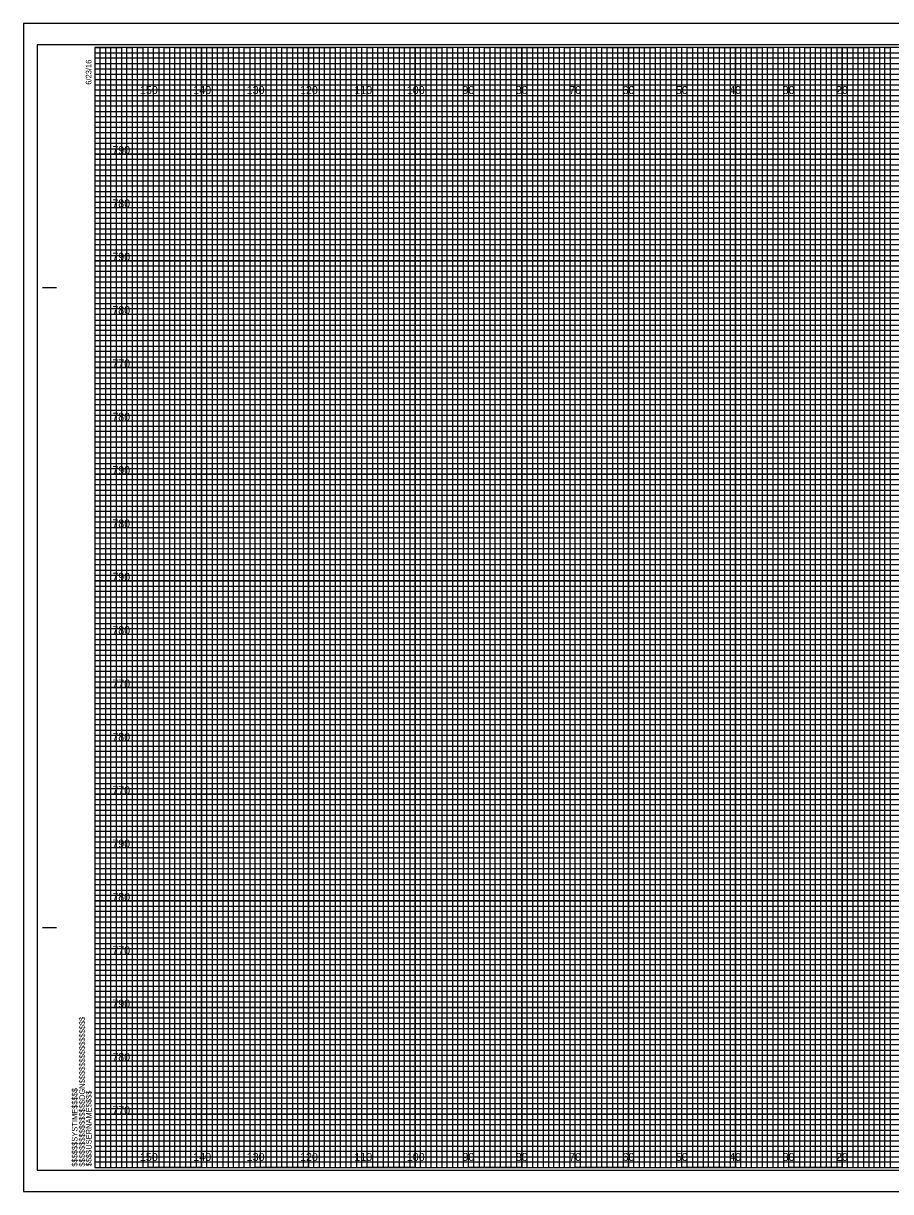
# Model space of a CAD drawing. Extents: x -13 to 323, y -5 to 215.
# Drawn here: x -13.4 to 149.1, y -4.5 to 214.5 of the extents above; entities that cross this region are included whole.
import ezdxf

# ---------------------------------------------------------------- set-up
doc = ezdxf.new("R2010")
doc.units = 0
for name, color, linetype in [('Exist Cross Section Cell', 7, 'Continuous'), ('Exist XS Center Line Elevation Label', 7, 'Continuous'), ('Exist XS Ground Line', 7, 'Continuous'), ('Prop CMT Pvmt Course 2', 7, 'Continuous'), ('Prop XS DDE', 7, 'Continuous'), ('Prop XS DDE Elevations', 7, 'Continuous'), ('Prop XS Elevation Labels', 7, 'Continuous'), ('Prop XS Offset Labels', 7, 'Continuous'), ('Sheet Cutting Line CELL', 7, 'Continuous'), ('Sheet DOT Grid CELL', 7, 'Continuous'), ('Sheet Plot Border Outside CELL', 7, 'Continuous')]:
    doc.layers.add(name, color=color, linetype=linetype)

msp = doc.modelspace()

# ---------------------------------------------------------------- linework, layer by layer
at = {"layer": 'Exist Cross Section Cell'}
for p, q in [((10, 210), (0, 210)), ((10, 0), (10, 210)), ((30, 210), (20, 210)), ((20, 210), (20, 0)), ((30, 0), (30, 210)), ((50, 210), (40, 210)), ((40, 210), (40, 0)), ((50, 0), (50, 210)), ((70, 210), (60, 210)), ((60, 210), (60, 0)), ((70, 0), (70, 210)), ((90, 210), (80, 210)), ((80, 210), (80, 0)), ((90, 0), (90, 210)), ((110, 210), (100, 210)), ((100, 210), (100, 0)), ((110, 0), (110, 210)), ((130, 210), (120, 210)), ((120, 210), (120, 0)), ((130, 0), (130, 210)), ((150, 210), (140, 210)), ((140, 210), (140, 0)), ((20, 0), (10, 0)), ((40, 0), (30, 0)), ((60, 0), (50, 0)), ((80, 0), (70, 0)), ((100, 0), (90, 0)), ((120, 0), (110, 0)), ((140, 0), (130, 0))]:
    msp.add_line(p, q, dxfattribs=at)
for points in [[(0, 200), (320, 200), (320, 190), (0, 190)], [(0, 180), (320, 180), (320, 170), (0, 170)], [(0, 160), (320, 160), (320, 150), (0, 150)], [(0, 140), (320, 140), (320, 130), (0, 130)], [(0, 120), (320, 120), (320, 110), (0, 110)], [(0, 100), (320, 100), (320, 90), (0, 90)], [(0, 80), (320, 80), (320, 70), (0, 70)], [(0, 60), (320, 60), (320, 50), (0, 50)], [(0, 40), (320, 40), (320, 30), (0, 30)], [(0, 20), (320, 20), (320, 10), (0, 10)]]:
    msp.add_lwpolyline(points, dxfattribs=at)
at = {"layer": 'Exist XS Center Line Elevation Label'}
for p, q in [((0, 209), (260, 209)), ((260, 207.98), (0, 207.98)), ((0, 207.98), (0, 207)), ((0, 207), (260, 207)), ((260, 205.89), (0, 205.89)), ((0, 205.89), (0, 204)), ((0, 204), (320, 204))]:
    msp.add_line(p, q, dxfattribs=at)
for points in [[(0, 203), (270, 203), (320, 203), (320, 202), (0, 202)], [(0, 201), (320, 201), (320, 199), (0, 199)], [(0, 198), (320, 198), (320, 197), (0, 196.98)], [(0, 196), (320, 196), (320, 194), (0, 194)], [(0, 193), (320, 193), (320, 192), (0, 192)], [(0, 191), (320, 191), (320, 189), (0, 189)], [(0, 188), (320, 188), (320, 187), (0, 187)], [(0, 186), (320, 186), (320, 184), (0, 184)], [(0, 183), (320, 183), (320, 182), (0, 182)], [(0, 181), (320, 181), (320, 179), (0, 179)], [(0, 178), (320, 178), (320, 177), (0, 177)], [(0, 176), (320, 176), (320, 173.95), (320, 173), (320, 172), (0, 172)], [(0, 174), (320, 174), (320, 173), (0, 173)], [(0, 171), (320, 171), (320, 169), (0, 169.03)], [(0, 169.03), (320, 169), (320, 168), (0, 168)], [(0, 167), (320, 167), (320, 166), (0, 166)], [(0, 164), (320, 164), (320, 163), (0, 163)], [(0, 162), (320, 162), (320, 161), (0, 161)], [(-0.07, 158.89), (320, 158.89), (320, 157.88), (-0.07, 157.88)], [(0, 157), (320, 157), (320, 156), (0, 156)], [(0, 154), (320, 154), (320, 153), (0, 153)], [(0, 152), (320, 152), (320, 151), (0, 151)], [(0, 149), (320, 149), (320, 148), (0, 148)], [(0, 147), (320, 147), (320, 146), (0, 146)], [(0, 144), (320, 144), (320, 143), (0, 143)], [(0, 142), (320, 142), (320, 141), (0, 141)], [(0, 139), (320, 139), (319.99, 137.98), (0, 138)], [(0, 137), (320, 137), (320, 136), (0, 136)], [(0, 134), (320, 134), (320, 133), (0, 133)], [(0, 132), (320, 132), (320, 131), (0, 131)], [(0, 129), (320, 129), (320, 128), (0, 128)], [(0, 127), (320, 127), (320, 126), (0, 126)], [(0, 124), (320, 124), (320, 123), (0, 123)], [(0, 122), (320, 122), (320, 121), (0, 121)], [(0, 119), (320, 119), (320, 118), (0, 118)], [(0, 116.99), (320.07, 116.91), (320, 116), (0, 116)], [(0, 114), (320, 114), (320, 113), (0, 113)], [(0, 112), (320, 112), (320, 111), (0, 111)], [(0, 109), (320, 109), (320, 108), (0, 108)], [(0, 107), (320, 107), (320, 106), (0, 106)], [(0, 104), (320, 104), (320, 103), (0, 103)], [(0, 102), (320, 102), (320, 101), (0, 101)], [(0, 99), (320, 99), (320, 98), (0, 98)], [(0, 97), (320, 97), (320, 96), (0, 96)], [(0, 94), (320, 94), (320, 93), (0, 93)], [(0, 92), (320, 92), (320, 91), (0, 91)], [(0, 89), (320, 89), (320, 88), (0, 88)], [(0, 87), (320, 87), (320, 86), (0, 86)], [(0, 84), (320, 84), (320, 83), (0, 83)], [(0, 82), (320, 82), (320, 81), (0, 81)], [(0, 79), (320, 79), (319.99, 77.98), (0, 78)], [(0, 77), (320, 77), (320, 76), (0, 76)], [(0, 74), (320, 74), (320, 73), (0, 73)], [(0, 72), (320, 72), (320, 71), (0, 71)], [(0, 69), (320, 69), (320, 68), (0, 68)], [(0, 67), (320, 67), (320, 66), (0, 66)], [(0, 64), (320, 64), (320, 63), (0, 63)], [(0, 62), (320, 62), (320, 61), (0, 61)], [(0, 59), (320, 59), (320, 58), (0, 58)], [(0, 56.99), (320.07, 56.91), (320, 56), (0, 56)], [(0, 54), (320, 54), (320, 53), (0, 53)], [(0, 52), (320, 52), (320, 51), (0, 51)], [(0, 49), (320, 49), (320, 48), (0, 48)], [(0, 47), (320, 47), (320, 46), (0, 46)], [(0, 44), (320, 44), (320, 43), (0, 43)], [(0, 42), (320, 42), (320, 41), (0, 41)], [(0, 39), (320, 39), (320, 38), (0, 38)], [(0, 37), (320, 37), (320, 36), (0, 36)], [(0, 34), (320, 34), (320, 33), (0, 33)], [(0, 32), (320, 32), (320, 31), (0, 31)], [(0, 29), (320, 29), (320, 28), (0, 28)], [(0, 27), (320, 27), (320, 26), (0, 26)], [(0, 24), (320, 24), (320, 23), (0, 23)], [(0, 22), (320, 22), (320, 21), (0, 21)], [(0, 19), (320, 19), (320, 18), (0, 18)], [(0, 17), (320, 17), (320, 16), (0, 16)], [(0, 14), (320, 14), (320, 13), (0, 13)], [(0, 12), (320, 12), (320, 11), (0, 11)], [(0, 9), (320, 9), (320, 8), (0, 8)], [(0, 7), (320, 7), (320, 6), (0, 6)], [(0, 4), (320, 4), (320, 3), (0, 3)], [(0, 2), (320, 2), (320, 1), (0, 1)]]:
    msp.add_lwpolyline(points, dxfattribs=at)
at = {"layer": 'Exist XS Ground Line'}
for points in [[(0, 210), (5, 210), (5, 0), (15, 0), (15, 210), (25, 210), (25, 0), (35, 0), (35, 210), (45, 210), (45, 0), (55, 0), (55, 210), (65, 210), (65, 0), (75, 0), (75, 210), (85, 210), (85, 0), (95, 0), (95, 210), (105, 210), (105, 0), (115, 0), (115, 210), (125, 210), (125, 0), (135, 0), (135, 210), (145, 210), (145, 0), (155, 0)], [(0, 205), (275, 205)], [(0, 185), (320, 185), (320, 195), (0, 195)], [(0, 165), (320, 165), (320, 175), (0, 175)], [(0, 145), (320, 145), (320, 155), (0, 155)], [(0, 125), (320, 125), (320, 135), (0, 135)], [(0, 105), (320, 105), (320, 115), (0, 115)], [(0, 85), (320, 85), (320, 95), (0, 95)], [(0, 65), (320, 65), (320, 75), (0, 75)], [(0, 45), (320, 45), (320, 55), (0, 55)], [(0, 25), (320, 25), (320, 35), (0, 35)], [(0, 5), (320, 5), (320, 15), (0, 15)]]:
    msp.add_lwpolyline(points, dxfattribs=at)
at = {"layer": 'Prop CMT Pvmt Course 2'}
msp.add_lwpolyline([(-10.8, -0.5), (322.4, -0.5), (322.4, 210.5), (-10.8, 210.5)], close=True, dxfattribs=at)
at = {"layer": 'Prop XS DDE'}
for p, q in [((-9.8, 165), (-7.3, 165)), ((-9.7, 165), (-7.2, 165)), ((-9.8, 45), (-7.3, 45)), ((-9.7, 45), (-7.2, 45)), ((0, 0), (0, 0)), ((0, 0), (0, 0)), ((0, 0), (0, 0)), ((0, 0), (0, 0)), ((0, 0), (0, 0)), ((0, 0), (0, 0)), ((0, 0), (0, 0))]:
    msp.add_line(p, q, dxfattribs=at)
msp.add_lwpolyline([(320, 210), (0, 210), (0, 0), (320, 0)], close=True, dxfattribs=at)
at = {"layer": 'Prop XS DDE Elevations'}
for points in [[(0, 0), (1, 0), (1, 210), (2, 210), (2, 0)], [(2, 0), (3, 0), (3, 210), (4, 210), (4, 0)], [(5, 0), (6, 0), (6, 210), (7, 210), (7, 0)], [(7, 0), (8, 0), (8, 210), (9, 210), (9, 0)], [(10, 0), (11, 0), (11, 210), (12, 210), (12, 0)], [(12, 0), (13, 0), (13, 210), (14, 210), (14, 0)], [(15, 0), (16, 0), (16, 210), (17, 210), (17, 0)], [(17, 0), (18, 0), (18, 210), (19, 210), (19, 0)], [(20, 0), (21, 0), (21, 210), (22, 210), (22, 0)], [(22, 0), (23, 0), (23, 210), (24, 210), (24, 0)], [(25, 0), (26, 0), (26, 210), (27, 210), (27, 0)], [(27, 0), (28, 0), (28, 210), (29, 210), (29, 0)], [(30, 0), (31, 0), (31, 210), (32, 210), (32, 0)], [(32, 0), (33, 0), (33, 210), (34, 210), (34, 0)], [(35, 0), (36, 0), (36, 210), (37, 210), (37, 0)], [(37, 0), (38, 0), (38, 210), (39, 210), (39, 0)], [(40, 0), (41, 0), (41, 210), (42, 210), (42, 0)], [(42, 0), (43, 0), (43, 210), (44, 210), (44, 0)], [(45, 0), (46, 0), (46, 210), (47, 210), (47, 0)], [(47, 0), (48, 0), (48, 210), (49, 210), (49, 0)], [(50, 0), (51, 0), (51, 210), (52, 210), (52, 0)], [(52, 0), (53, 0), (53, 210), (54, 210), (54, 0)], [(55, 0), (56, 0), (56, 210), (57, 210), (57, 0)], [(57, 0), (58, 0), (58, 210), (59, 210), (59, 0)], [(60, 0), (61, 0), (61, 210), (62, 210), (62, 0)], [(62, 0), (63, 0), (63, 210), (64, 210), (64, 0)], [(65, 0), (66, 0), (66, 210), (67, 210), (67, 0)], [(67, 0), (68, 0), (68, 210), (69, 210), (69, 0)], [(70, 0), (71, 0), (71, 210), (72, 210), (72, 0)], [(72, 0), (73, 0), (73, 210), (74, 210), (74, 0)], [(75, 0), (76, 0), (76, 210), (77, 210), (77, 0)], [(77, 0), (78, 0), (78, 210), (79, 210), (79, 0)], [(80, 0), (81, 0), (81, 210), (82, 210), (82, 0)], [(82, 0), (83, 0), (83, 210), (84, 210), (84, 0)], [(85, 0), (86, 0), (86, 210), (87, 210), (87, 0)], [(87, 0), (88, 0), (88, 210), (89, 210), (89, 0)], [(90, 0), (91, 0), (91, 210), (92, 210), (92, 0)], [(92, 0), (93, 0), (93, 210), (94, 210), (94, 0)], [(95, 0), (96, 0), (96, 210), (97, 210), (97, 0)], [(97, 0), (98, 0), (98, 210), (99, 210), (99, 0)], [(100, 0), (101, 0), (101, 210), (102, 210), (102, 0)], [(102, 0), (103, 0), (103, 210), (104, 210), (104, 0)], [(105, 0), (106, 0), (106, 210), (107, 210), (107, 0)], [(107, 0), (108, 0), (108, 210), (109, 210), (109, 0)], [(110, 0), (111, 0), (111, 210), (112, 210), (112, 0)], [(112, 0), (113, 0), (113, 210), (114, 210), (114, 0)], [(115, 0), (116, 0), (116, 210), (117, 210), (117, 0)], [(117, 0), (118, 0), (118, 210), (119, 210), (119, 0)], [(120, 0), (121, 0), (121, 210), (122, 210), (122, 0)], [(122, 0), (123, 0), (123, 210), (124, 210), (124, 0)], [(125, 0), (126, 0), (126, 210), (127, 210), (127, 0)], [(127, 0), (128, 0), (128, 210), (129, 210), (129, 0)], [(130, 0), (131, 0), (131, 210), (132, 210), (132, 0)], [(132, 0), (133, 0), (133, 210), (134, 210), (134, 0)], [(135, 0), (136, 0), (136, 210), (137, 210), (137, 0)], [(137, 0), (138, 0), (138, 210), (139, 210), (139, 0)], [(140, 0), (141, 0), (141, 210), (142, 210), (142, 0)], [(142, 0), (143, 0), (143, 210), (144, 210), (144, 0)], [(145, 0), (146, 0), (146, 210), (147, 210), (147, 0)], [(147, 0), (148, 0), (148, 210), (149, 210), (149, 0)]]:
    msp.add_lwpolyline(points, dxfattribs=at)
at = {"layer": 'Sheet Cutting Line CELL'}
for p, q in [((323.3, 214.5), (-13.4, 214.5)), ((-13.4, 214.5), (-13.4, -4.5)), ((-13.4, -4.5), (323.3, -4.5))]:
    msp.add_line(p, q, dxfattribs=at)
at = {"layer": 'Sheet DOT Grid CELL'}
for p, q in [((10, 0), (10, 210)), ((20, 0), (20, 210)), ((30, 0), (30, 210)), ((40, 0), (40, 210)), ((50, 0), (50, 210)), ((60, 0), (60, 210)), ((70, 0), (70, 210)), ((80, 0), (80, 210)), ((90, 0), (90, 210)), ((100, 0), (100, 210)), ((110, 0), (110, 210)), ((120, 0), (120, 210)), ((130, 0), (130, 210)), ((140, 0), (140, 210)), ((0, 200), (320, 200)), ((0, 190), (320, 190)), ((0, 180), (320, 180)), ((0, 170), (320, 170)), ((0, 160), (320, 160)), ((0, 150), (320, 150)), ((0, 140), (320, 140)), ((0, 130), (320, 130)), ((0, 120), (320, 120)), ((0, 110), (320, 110)), ((0, 100), (320, 100)), ((0, 90), (320, 90)), ((0, 80), (320, 80)), ((0, 70), (320, 70)), ((0, 60), (320, 60)), ((0, 50), (320, 50)), ((0, 40), (320, 40)), ((0, 30), (320, 30)), ((0, 20), (320, 20)), ((0, 10), (320, 10))]:
    msp.add_line(p, q, dxfattribs=at)
at = {"layer": 'Sheet Plot Border Outside CELL'}
msp.add_lwpolyline([(-13.4, -4.5), (323.3, -4.5), (323.3, 214.5), (-13.4, 214.5)], close=True, dxfattribs=at)

# ---------------------------------------------------------------- texts
at = {"layer": 'Prop XS DDE'}
for s, p in [('6/23/16', (-0.65, 203)), ('$$$$$$$$$$$$$$$$DGN$$$$$$$$$$$$$$$$', (-1.88, 0.18)), ('$$$$$$SYSTIME$$$$$', (-3.26, 0.18)), ('$$$$USERNAME$$$$', (-0.62, 0.23))]:
    msp.add_text(s, height=1.05, rotation=90, dxfattribs=at).set_placement(p)
at = {"layer": 'Prop XS Elevation Labels'}
for s, p in [('790', (3.26, 190)), ('780', (3.26, 180)), ('790', (3.26, 170)), ('780', (3.26, 160)), ('770', (3.26, 150)), ('780', (3.26, 140)), ('790', (3.26, 130)), ('780', (3.26, 120)), ('790', (3.26, 110)), ('780', (3.26, 100)), ('770', (3.26, 90)), ('780', (3.26, 80)), ('770', (3.26, 70)), ('790', (3.26, 60)), ('780', (3.26, 50)), ('770', (3.26, 40)), ('790', (3.26, 30)), ('780', (3.26, 20)), ('770', (3.26, 10))]:
    msp.add_text(s, height=1.5, dxfattribs=at).set_placement(p)
at = {"layer": 'Prop XS Offset Labels'}
for s, p in [('150', (8.44, 201.25)), ('140', (18.44, 201.25)), ('130', (28.44, 201.25)), ('120', (38.44, 201.25)), ('110', (48.62, 201.25)), ('100', (58.44, 201.25)), ('90', (68.86, 201.25)), ('80', (78.86, 201.25)), ('70', (88.86, 201.25)), ('60', (98.86, 201.25)), ('50', (108.86, 201.25)), ('40', (118.86, 201.25)), ('30', (128.86, 201.25)), ('20', (138.86, 201.25)), ('150', (8.44, 1.25)), ('140', (18.44, 1.25)), ('130', (28.44, 1.25)), ('120', (38.44, 1.25)), ('110', (48.62, 1.25)), ('100', (58.44, 1.25)), ('90', (68.86, 1.25)), ('80', (78.86, 1.25)), ('70', (88.86, 1.25)), ('60', (98.86, 1.25)), ('50', (108.86, 1.25)), ('40', (118.86, 1.25)), ('30', (128.86, 1.25)), ('20', (138.86, 1.25))]:
    msp.add_text(s, height=1.5, dxfattribs=at).set_placement(p)

doc.saveas('drawing.dxf')
